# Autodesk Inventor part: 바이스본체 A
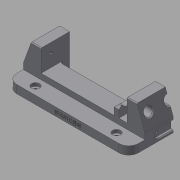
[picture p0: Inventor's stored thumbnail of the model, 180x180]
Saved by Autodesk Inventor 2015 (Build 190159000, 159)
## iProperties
Created: 2017-04
Part Number: 바이스본체 A
Material: 일반
Document SubType Name: Modeling
Designer: mduedu
Density: 1 g/cm^3
Appearance: 기본값
Mass: 119.631 g
Surface Area: 276.734 cm^2
Volume: 119.631 cm^3
Author: mduedu
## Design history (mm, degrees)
sketch "스케치1"
  geometry: L1 (-75, 0)-(75, 0); L2 (-75, 0)-(-75, 17); L3 (-53, 17)-(53, 17); L4 (75, 17)-(75, 0); L5 (-75, 17)-(-65.173, 44); L6 (-65.173, 44)-(-53, 44); L7 (-53, 44)-(-53, 17); L8 (0, 0)-(0, 17); L9 (75, 17)-(65.173, 44); L10 (65.173, 44)-(53, 44); L11 (53, 44)-(53, 17); 1 further point
  constraints: 22 end point, 4 perpendicular, 2 horizontal alignment, 2 midpoint, 2 symmetric about line, 1 coincident, 1 collinear, 1 horizontal, 1 vertical
  dimensions: "d0" = 150 distance of L1.start L1.end; "d1" = 17 distance of L1.start L2.end; "d2" = 27 distance of L3.start L6.end; "d3" = 22 distance of L3.start L2.end; "d4" = 70 deg angle of L3 L5; "d54" = 20 deg angle of L9 L4
extrude "돌출1" new body sketch "스케치1" stored distance "d5" = 70; taper "d6" = 0 deg
sketch "스케치2"
  geometry: L1 (0, 70)-(106, 70) reference; L2 (106, 70)-(106, 0) reference; L3 (106, 0)-(0, 0) reference; L4 (0, 47)-(106, 47); L5 (106, 47)-(106, 23); L6 (106, 23)-(0, 23); L7 (0, 23)-(0, 47); L8 (0, 70)-(0, 0) reference; 2 further points
  constraints: 8 end point, 2 parallel, 2 point on line, 1 horizontal, 1 horizontal alignment, 1 midpoint, 1 perpendicular
  dimensions: "d7" = 24 distance between parallel lines of L6 L4
extrude "돌출2" cut sketch "스케치2" stored distance "d9" = 70; taper "d10" = 0 deg
sketch "스케치3"
  geometry: L1 (22, -23)-(128, -23) reference; L2 (128, -47)-(22, -47) reference; L3 (22, -18)-(128, -18); L4 (128, -52)-(22, -52); L5 (22, -18)-(22, -52); L6 (128, -18)-(128, -52); 1 further point
  constraints: 8 end point, 3 parallel, 2 point on line, 1 perpendicular
  dimensions: "d11" = 5 distance between parallel lines of L3 L1; "d12" = 5 distance between parallel lines of L4 L2
extrude "돌출3" cut sketch "스케치3" distance "d13" = 12; taper "d14" = 0 deg
fillet "모깎기1" dims "d15" = 3, "d16" = 3
sketch "스케치4"
  geometry: L1 (103, 23)-(3, 23) reference; L2 (0, 26)-(0, 0) reference; L3 (106, 0)-(0, 0) reference; L4 (106, 26)-(106, 0) reference; L5 (96, 0)-(90, 0); L6 (90, 0)-(90, 19.5); L7 (96, 19.5)-(96, 0); L8 (90, 19.5)-(96, 19.5); A1 r 3 centre (3, 26) between (0, 26) and (3, 23) reference; A2 r 3 centre (103, 26) between (103, 23) and (106, 26) reference; 1 further point
  constraints: 8 end point, 2 perpendicular, 1 horizontal, 1 parallel, 1 point on line
  dimensions: "d17" = 10 distance between parallel lines of L7 L4; "d18" = 6 distance between parallel lines of L7 L6; "d27" = 3.5 distance between parallel lines of L8 L1
extrude "돌출4" join sketch "스케치4" distance "d19" = 12; taper "d20" = 0 deg
chamfer "모따기1" distance "d21" = 3; stored, may be unused: second distance "d22" = 2, angle "d23" = 45 deg
chamfer "모따기2" distance "d24" = 3; stored, may be unused: second distance "d25" = 2, angle "d26" = 45 deg
sketch "스케치5"
  geometry: L1 (-15.5, 35.8)-(-15.5, -25.8) reference; L2 (19.5, 0)-(0, 0) reference; C1 r 6.5 at (9.5, 15); 1 further point
  constraints: 1 centre point
  dimensions: "d28" = 13 diameter of C1; "d30" = 15 distance from line of C1.centre L2; "d31" = 25 distance from line of C1.centre L1
extrude "돌출5" cut sketch "스케치5" stored distance "d32" = 12; taper "d33" = 0 deg
sketch "스케치6"
  geometry: C1 r 5 at (-10, 15); C2 r 5 at (-60, 15); A1 r 6.5 centre (-10, 15) between (-15.766, 12) and (-4.234, 12) reference; A2 r 6.5 centre (-60, 15) between (-65.766, 12) and (-54.234, 12) reference; 1 further point
  constraints: 2 centre point, 2 coincident
  dimensions: "d34" = 10 diameter of C1; "d35" = 10 diameter of C2 (= d34)
extrude "돌출6" cut sketch "스케치6" stored distance "d36" = 12; taper "d37" = 0 deg
chamfer "모따기3" distance "d38" = 1; stored, may be unused: second distance "d39" = 2, angle "d40" = 45 deg
chamfer "모따기4" distance "d41" = 1; stored, may be unused: second distance "d42" = 2, angle "d43" = 45 deg
sketch "스케치7"
  geometry: L1 (-35, 35.8)-(-35, -25.8) reference; L2 (-70, 0)-(0, 0) reference; C1 r 5 at (-35, 15); 1 further point
  constraints: 1 centre point, 1 point on line
  dimensions: "d44" = 10 diameter of C1; "d45" = 15 distance from line of C1.centre L2
extrude "돌출7" cut sketch "스케치7" stored distance "d46" = 12; taper "d47" = 0 deg
chamfer "모따기5" distance "d48" = 1; stored, may be unused: second distance "d49" = 2, angle "d50" = 45 deg
node "작업축1"
sketch "스케치8"
  geometry: L1 (-105, 32)-(105, 32) reference; L2 (58, 32)-(64, 32); L3 (64, 32)-(64, 40); L4 (64, 40)-(58, 40); L5 (58, 40)-(58, 32); L6 (53, 38)-(53, 26) reference; 1 further point
  constraints: 8 end point, 2 parallel, 1 horizontal, 1 perpendicular, 1 point on line
  dimensions: "d51" = 5 distance from line of L6 L2.start; "d52" = 6 distance of L3.end L4.end; "d53" = 16 diameter of L4 L1
revolve "회전1" sketch "스케치8" stored, may be unused: angle "d55" = 90 deg
fillet "모깎기2"
chamfer "모따기6" distance "d56" = 1; stored, may be unused: second distance "d57" = 2, angle "d58" = 45 deg
sketch "스케치9"
  geometry: L1 (17.5, 3)-(52.5, 3); L2 (52.5, 13)-(17.5, 13); L3 (70, 0)-(0, 0) reference; L4 (17.5, 8)-(52.5, 8); A1 r 5 centre (17.5, 8) between (17.5, 13) and (17.5, 3); A2 r 5 centre (52.5, 8) between (52.5, 3) and (52.5, 13); 3 further points
  constraints: 6 end point, 4 point on circle, 3 tangent, 2 centre point, 2 midpoint, 2 parallel, 1 horizontal, 1 vertical alignment
  dimensions: "d59" = 35 distance of L4.start L4.end; "d61" = 5 radius of A2; "d62" = 8 distance between parallel lines of L3 L4
extrude "돌출8" cut sketch "스케치9" distance "d63" = 3; taper "d64" = 0 deg
chamfer "모따기7" distance "d65" = 1; stored, may be unused: second distance "d66" = 2, angle "d67" = 45 deg
chamfer "모따기8" distance "d68" = 1; stored, may be unused: second distance "d69" = 2, angle "d70" = 45 deg
feature "분할1"
sketch "스케치10"
  geometry: L1 (35, 27)-(0, 27) reference; L2 (0, 0)-(0, 27) reference; 1 further point
  dimensions: "d85" = 11.5 distance from line of point (12, 15.5) L1; "d86" = 12 distance from line of point (12, 15.5) L2
hole "구멍1" sketch "스케치10" at (12, 15.5) diameter "d71" = 3.242; stored, may be unused: countersink angle "d75" = 90 deg, drill point angle "d77" = 120 deg; dims "d72" = 6, "d73" = 4, "d74" = 2, "d76" = 8
sketch "스케치11"
  geometry: A1 r 5 centre (17.5, 8) between (17.5, 13) and (17.5, 3) reference; 1 further point
  constraints: 1 coincident
hole "구멍3" sketch "스케치11" at (17.5, 8) diameter "d78" = 2.459; stored, may be unused: countersink angle "d82" = 90 deg, drill point angle "d84" = 120 deg; dims "d79" = 4.5, "d80" = 4, "d81" = 2, "d83" = 6
sketch "스케치13"
  geometry: L1 (75, 0)-(75, 35) reference; L2 (-75, 0)-(-75, 35) reference; L3 (-75, 35)-(75, 35); L4 (75, 35)-(75, 55); L5 (75, 55)-(-75, 55); L6 (-75, 55)-(-75, 35); 1 further point
  constraints: 8 end point, 2 parallel, 1 horizontal, 1 perpendicular, 1 point on line
  dimensions: "d90" = 20 distance between parallel lines of L5 L3; "d94" = 150 distance of L4.end L5.end (derived)
extrude "돌출9" join sketch "스케치13" distance "d92" = 10; taper "d93" = 0 deg
sketch "스케치14"
  geometry: L1 (-75, -35)-(-75, -55) reference; L2 (75, -55)-(75, -35) reference; L3 (-75, -45)-(75, -45); 3 further points
  constraints: 2 end point, 2 midpoint, 2 point on line
  dimensions: "d95" = 50 horizontal distance of point (-50, -45) point (0, 0); "d96" = 100 distance of point (50, -45) point (-50, -45)
fillet "모깎기3" dims "d97" = 12
chamfer "모따기9" distance "d98" = 1; stored, may be unused: second distance "d99" = 2, angle "d100" = 45 deg
hole "구멍4" sketch "스케치14" diameter "d101" = 4.134; stored, may be unused: countersink angle "d105" = 90 deg, drill point angle "d107" = 118 deg; dims "d102" = 6, "d103" = 10, "d104" = 4, "d106" = 8
sketch "스케치15"
  geometry: L1 (0, 0)-(126, 0) reference; 3 further points
  constraints: 1 midpoint, 1 vertical alignment, 1 other
  dimensions: "d109" = 5 distance from line of point (63, 5) L1
feature "엠보싱2" sketch "스케치15" dims "d0" = 150, "d1" = 17, "d2" = 27, "d3" = 22, "d4" = 70 deg, "d54" = 20 deg, "d110" = 0.5, "d111" = 0
node "솔리드1"
mirror "대칭1"
mirror "대칭2"
mirror "대칭3"
mirror "대칭4"
node "투영된 루프1"
